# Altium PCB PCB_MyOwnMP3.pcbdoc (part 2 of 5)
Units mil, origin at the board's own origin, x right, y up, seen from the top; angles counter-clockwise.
Board outline 3605 x 4860 mil, 6 copper layers (Top Layer, Inner1, Inner2, Inner3, Inner4, Bottom Layer); 291 components, 261 nets, 1070 pads, 1658 vias.
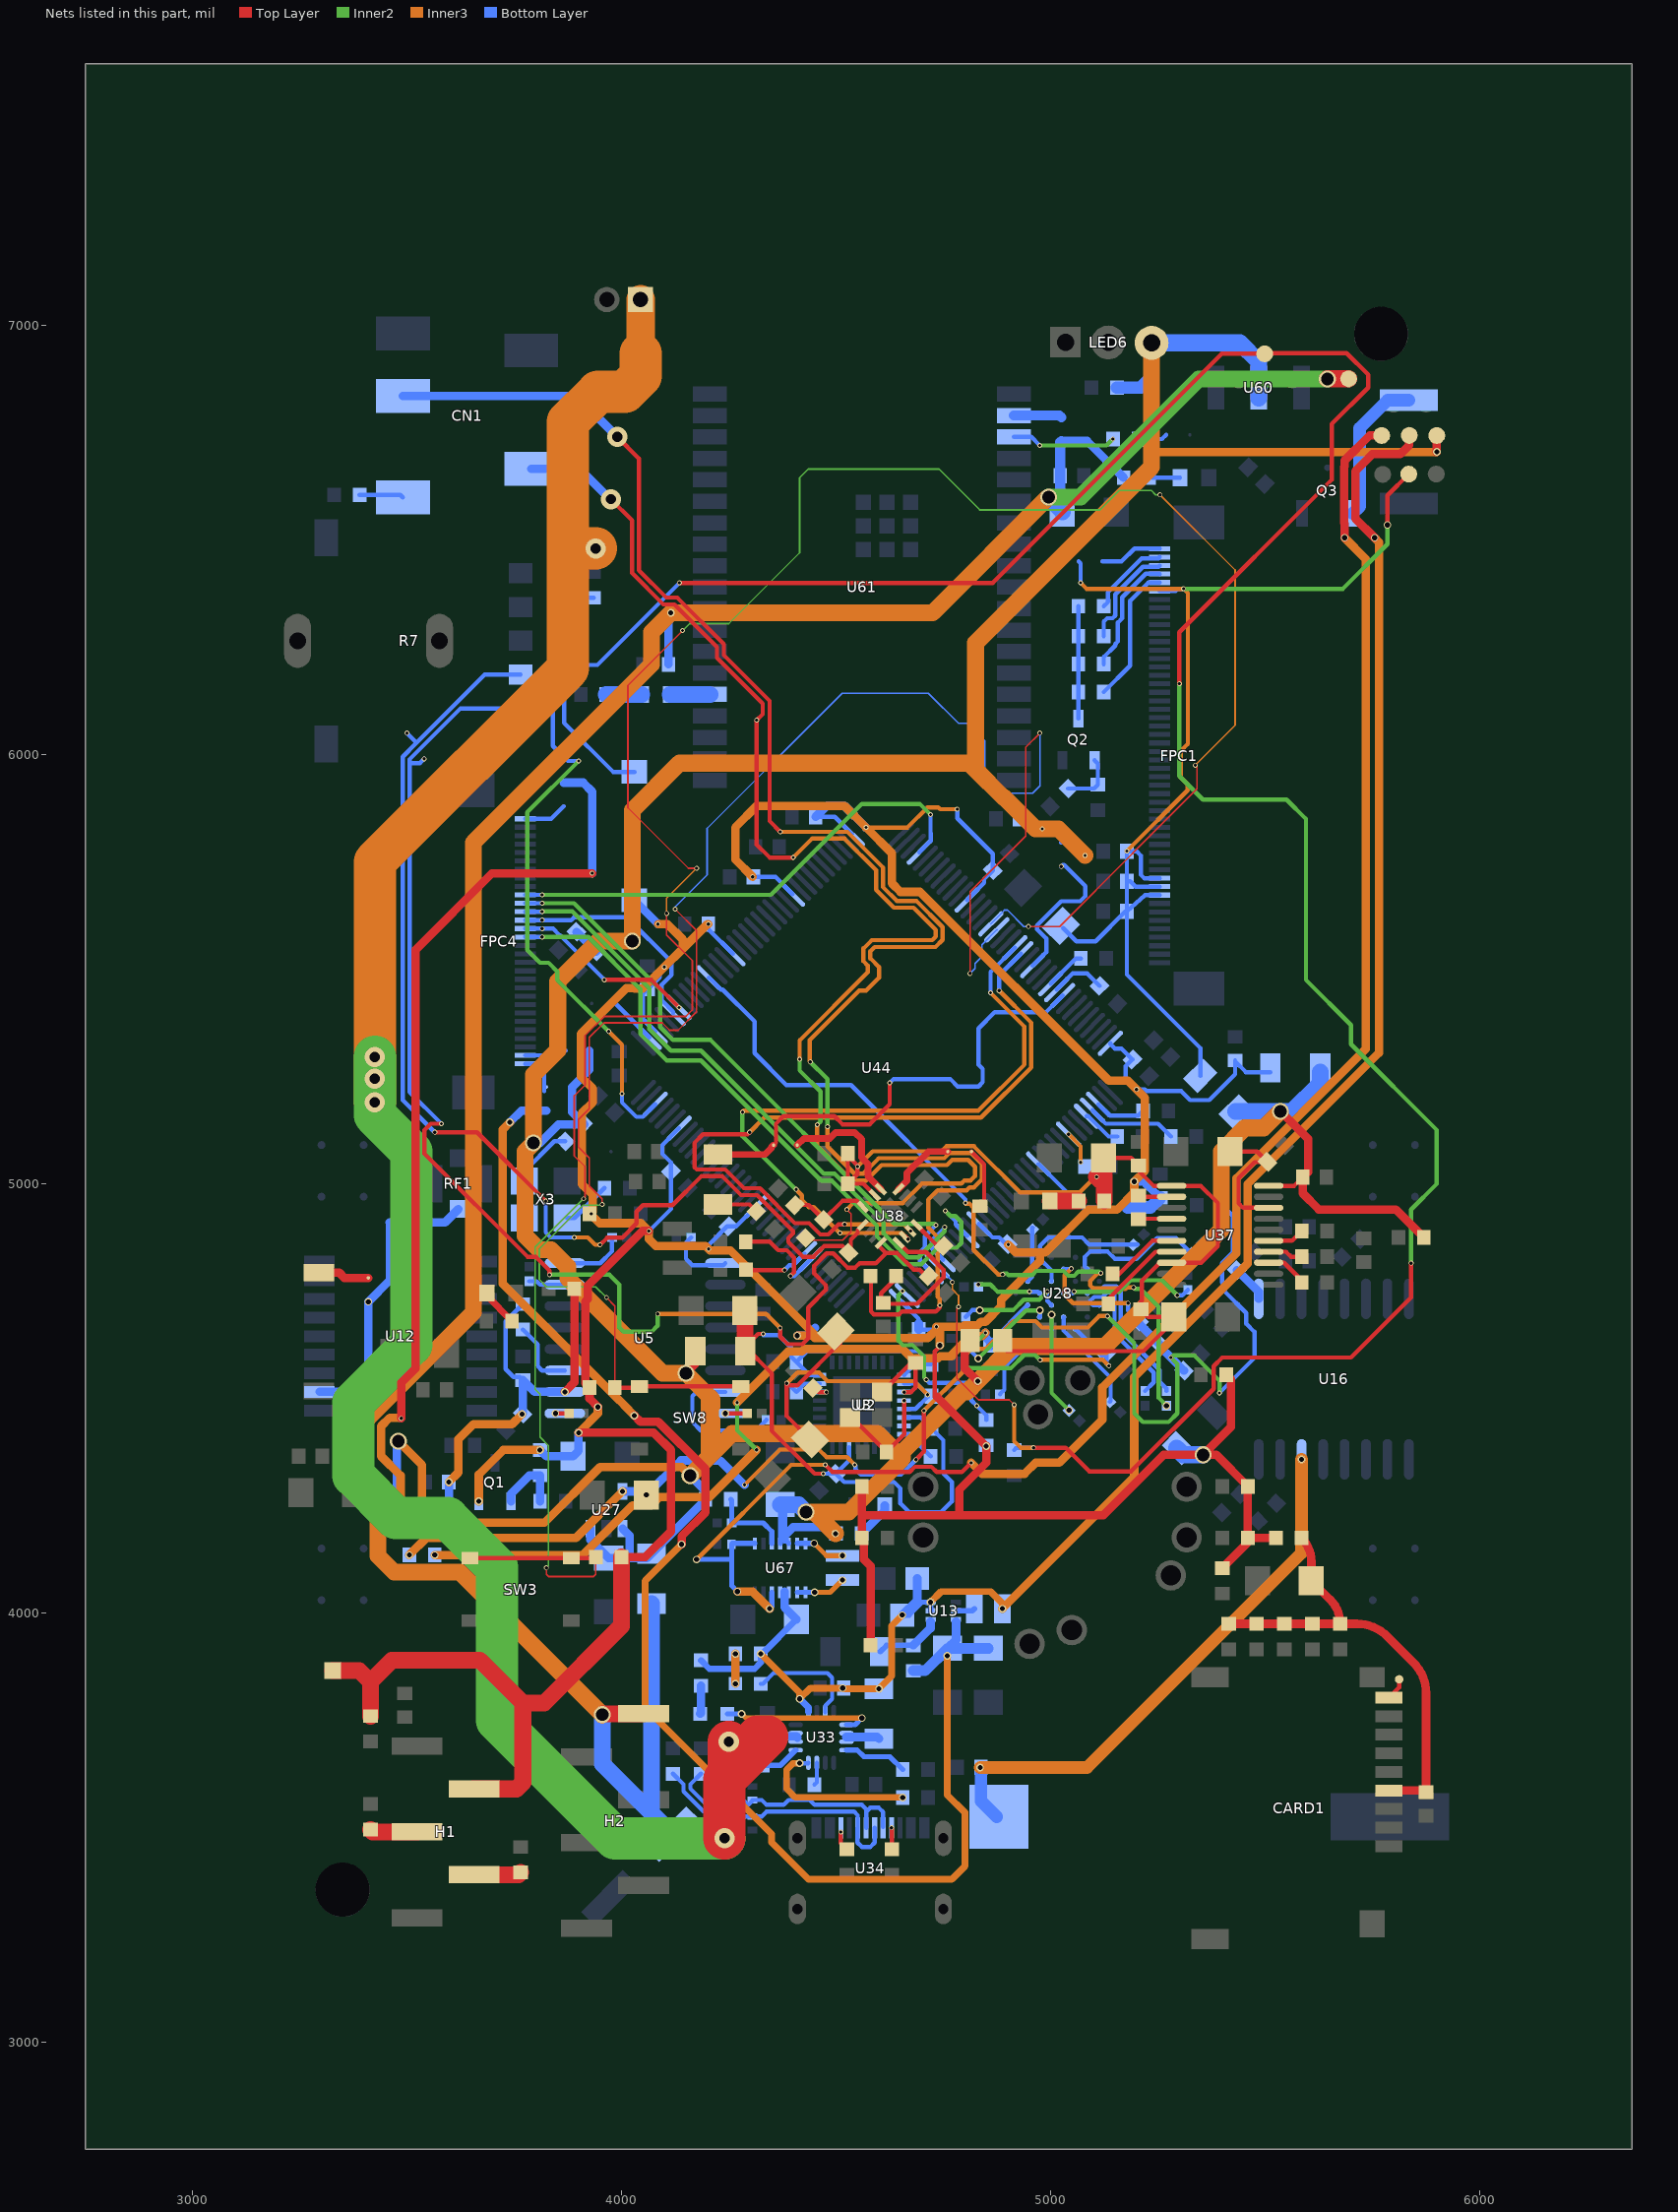
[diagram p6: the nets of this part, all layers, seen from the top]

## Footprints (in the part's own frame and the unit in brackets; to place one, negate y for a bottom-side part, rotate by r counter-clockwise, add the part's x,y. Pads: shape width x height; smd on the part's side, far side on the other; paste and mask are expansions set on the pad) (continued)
WIFI-SMD_ESP32-WROVER-E-N8R2 [mm]
  rect 2x0.9 smd: 1(-9,11.43) 2(-9,10.16) 3(-9,8.89) 4(-9,7.62) 5(-9,6.35) 6(-9,5.08) 7(-9,3.81) 8(-9,2.54) 9(-9,1.27) 10(-9,0) 11(-9,-1.27) 12(-9,-2.54) 13(-9,-3.81) 14(-9,-5.08) 15(-9,-6.35) 16(-9,-7.62) 17(-9,-8.89) 18(-9,-10.16) 19(-9,-11.43) 20(9,-11.43) 21(9,-10.16) 22(9,-8.89) 23(9,-7.62) 24(9,-6.35) 25(9,-5.08) 26(9,-3.81) 27(9,-2.54) 28(9,-1.27) 29(9,0) 30(9,1.27) 31(9,2.54) 32(9,3.81) 33(9,5.08) 34(9,6.35) 35(9,7.62) 36(9,8.89) 37(9,10.16) 38(9,11.43)
  rect 0.9x0.9 smd: 39(-2.89,2.22) 39(-2.89,3.62) 39(-2.89,5.02) 39(-1.49,2.22) 39(-1.49,3.62) 39(-1.49,5.02) 39(-0.09,2.22) 39(-0.09,3.62) 39(-0.09,5.02)
  silkscreen extent -9.72,-12.53 9,18.87
WQFN-16_L3.0-W3.0-P0.50-TL-EP1.6 [mm]
  rect 0.8x0.28 smd: 1(-1.5,0.749) 2(-1.5,0.249) 3(-1.5,-0.249) 4(-1.5,-0.749) 9(1.5,-0.749) 10(1.5,-0.249) 11(1.5,0.249) 12(1.5,0.749)
  rect 0.28x0.8 smd: 5(-0.749,-1.5) 6(-0.249,-1.5) 7(0.249,-1.5) 8(0.749,-1.5) 13(0.749,1.5) 14(0.249,1.5) 15(-0.249,1.5) 16(-0.749,1.5)
  rect 1.6x1.6 smd: 17(0,0)
  silkscreen extent -2.38,-1.72 1.72,1.72

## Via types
v1: diameter 11.42, hole 7.48, Top Layer to Bottom Layer, 1536 vias
v2: diameter 17.72, hole 11.81, Top Layer to Bottom Layer, 85 vias
v3: diameter 39.37, hole 29.53, Top Layer to Bottom Layer, 11 vias
v4: diameter 11.81, hole 7.87, Top Layer to Bottom Layer, 8 vias
v5: diameter 47.24, hole 23.62, Top Layer to Bottom Layer, 8 vias
v6: diameter 19.68, hole 11.81, Top Layer to Bottom Layer, 4 vias
v7: diameter 24.41, hole 12.2, Top Layer to Bottom Layer, 3 vias
v8: diameter 11.4, hole 7.5, Top Layer to Bottom Layer, 3 vias

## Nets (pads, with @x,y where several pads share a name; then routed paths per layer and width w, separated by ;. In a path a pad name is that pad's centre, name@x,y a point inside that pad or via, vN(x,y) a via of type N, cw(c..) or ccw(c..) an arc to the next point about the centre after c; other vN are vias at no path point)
1V8_PHY: C42.2 C43.2 C44.2 C80.2 U3.15 U3.26 U3.29 | length 947.7
  Top Layer w10: C42.2@4439.34,4404.34 4385,4458.67 v1(4385,4535) 4390,4530 4410,4530 4509.34,4629.34 C44.2@4509.34,4665.66
  Inner3 w10: v1(4385,4535) 4410,4560 4460,4560 4480,4540 4681.84,4540 v1(4713.54,4508.31)
  Bottom Layer w10: v1(4385,4535) 4387.56,4535 C43.2@4407.56,4515 4426.85,4534.29 U3.15@4461.58,4534.29 ; U3.29@4658.42,4475.16 4685.16,4475.16 4713.54,4503.54 v1(4713.54,4508.31) 4687.63,4534.21 U3.26@4658.42,4534.21
1V8_VCCQ: C73.1 C74.1 R99.2 U28.D1 U28.E4 | length 2390.2
  Inner2 w10: v1(4269.49,4490) 4269.49,4425.51 v1(4315,4380) ; v1(4848.29,4652.74) 4795,4599.45 4795,4585 4808.54,4571.46 4810.48,4571.46 4811.78,4570.16 4906.92,4570.16 4938.38,4601.62 4963.52,4601.62 v1(4975.51,4589.63)
  Inner3 w10: v1(4975.51,4589.63) 4975.88,4590 5121.69,4590 v1(5135.84,4575.84)
  Inner3 w19.68: v2(3564.66,4135) 3910,4135 4025.31,4250.31 4068.22,4250.31 4087.9,4270 4205,4270 v1(4315,4380) ; v1(4269.49,4490) 4388.82,4609.33 4420.63,4609.33 4426.3,4615 4655,4615 4676.93,4593.07 4737.62,4593.07 4742.1,4597.55 4770,4597.55 4770,4602.29 4812.71,4645 4840.55,4645 v1(4848.29,4652.74)
  Bottom Layer w10: C74.1@4860,4630.7 U28.E4@4946.48,4717.16 ; U28.D1@5057.84,4661.48 5119.83,4599.49 C73.1@5125.51,4599.49 ; C73.1@5130.51,4604.49 5130.51,4581.18 v1(5135.84,4575.84)
  Bottom Layer w19.68: v1(4848.29,4652.74) 4848.29,4642.41 4860,4630.7 C74.1@4860,4622.56
1V8_VDD: C39.2 C70.2 C71.1 C72.1 JP13.2 R99.1 R111.2 U27.5 U28.B4 | length 5916.7
  Top Layer w10: v1(4686.09,4357.16) 4704.83,4375.9 v1(4704.83,4471.22)
  Top Layer w19.68: v1(3486.57,4453.43) 3486.57,4536.57 3520,4570 3520,5545 3698.43,5723.43 v1(3931.57,5723.43)
  Inner2 w10: v1(5132.49,4691.3) 5195,4628.79 5195,4465 5215,4445 5275,4445 5295,4465 5295,4580.27 v1(5280.36,4594.91) 5285.46,4600 5335,4600 5393.46,4541.54 v1(5393.46,4512.3)
  Inner3 w10: v1(4286.57,4298.43) 4368.96,4380.83 4460,4380.83 4477.91,4362.91 4525.62,4362.91 v1(4543.53,4345) ; v1(4704.83,4471.22) 4795,4561.39 4795,4595 4815,4615 4848.61,4615 4913.61,4680 4965,4680 4980,4665 5086.39,4665 5113.09,4691.69 5132.1,4691.69 v1(5132.49,4691.3) ; v1(5048.1,4802.32) 5032.87,4787.1 5032.87,4741.01 5052.27,4721.61 v1(5180.59,4721.61)
  Inner3 w19.68: v1@3485,4455 3460,4455 3440,4435 3440,4365 3485,4320 3485,4235.34 3545.34,4175 ; v2(3505.34,4135) 3545.34,4175 ; v2(4002.4,4283.31) 3894.09,4175 3545.34,4175
  Bottom Layer w10: v1(4543.53,4345) 4545,4343.53 4545,4335 4557.5,4322.5 4651.43,4322.5 v1(4686.09,4357.16) ; U28.B4@5030,4800.68 5046.45,4800.68 v1(5048.1,4802.32) ; v1(5180.59,4721.61) 5180.59,4704.68 C71.1@5205.8,4679.48 ; v1(5393.46,4512.3) 5475,4593.84 5475,4655 5455.98,4674.02 5455.98,4699.02 5405.98,4749.02 5405.98,4763.4 5399.66,4769.73 5399.66,4814.66 5425,4840 5425,4924.66 R111.2@5399.66,4950
  Bottom Layer w19.68: JP13.2@3865,5934.53 3910.47,5934.53 3931.57,5913.43 v1(3931.57,5723.43) ; v2(4002.4,4283.31) 4049.68,4283.31 v2(4057.99,4275) 4138.5,4355.51 4174.71,4355.51 4175.22,4355 4230,4355 v1(4286.57,4298.43) ; C71.1@5205.8,4679.48 5205.8,4674.48 C72.1@5255.8,4624.48 5255.8,4619.48 v1(5280.36,4594.91) C70.2@5310.8,4564.48
3V3: C13.2 C59.2 C60.1 C61.1 C62.1 C63.1 C64.1 C65.1 C66.1 C67.1 C68.1 C69.1 C123.1 H1.4 JP4.2 JP5.2 KEY2.1 Q1.2 R15.1 R17.1 R47.2 R49.2 R50.2 R51.2 R52.1 R53.1 R54.1 R58.2 R73.2 R87.2 R88.2 TP2.1 U18.2 U29.2 U41.2 U44.17 U44.30 U44.39 U44.52 U44.62 U44.72 U44.84 U44.108 U44.131 U44.144 | length 12258.6
  Top Layer w10: 4735.07,4503.63 4730.23,4508.47 4730.23,4609.43 4741.98,4621.19 v2(4741.98,4623.22)
  Top Layer w19.68: v2(3900,4420) 4075,4420 4115,4380 4115,4190 4055,4130 R87.2@3999.66,4130 ; v2(3945,4480) 3925.34,4499.66 R88.2@3925.34,4525 3915.67,4534.67 3915.67,4725.74 3921.36,4731.44 3921.36,4762.83 4048.53,4890 v1(4063.91,4890) ; R52.1@4560.34,4295 4560.34,4227.58 ; R51.2@4580.34,3925 4580.34,4109.66 4565,4125 4565,4170.34 R49.2@4560.34,4175 4560.34,4227.58 ; 4735.07,4503.63 v2(4850,4388.7) 4850,4350 4787.58,4287.58 4787.58,4227.58 ; R73.2@5400,4104.66 5459.66,4164.32 R50.2@5459.66,4175 ; R53.1@5409.66,4555 5420,4544.66 5420,4433.04 v3(5355.44,4368.48) ; R54.1@5525.34,4175 R50.2@5459.66,4175 ; 4560.34,4227.58 4787.58,4227.58 ; 4787.58,4227.58 5122.58,4227.58 5263.48,4368.48 v3(5355.44,4368.48) ; v3(5355.44,4368.48) 5386.18,4368.48 R47.2@5459.66,4295 R50.2@5459.66,4175
  Top Layer w39.37: TP2.1@3326.8,3866.02 3388.98,3866.02 3415,3840 ; U29.2@3415,3759.66 3415,3840 ; H1.4@3656.54,3590 3755,3590 3770,3605 3770,3790 ; R87.2@3999.66,4130 3999.66,3969.66 3820,3790 3770,3790 ; 3415,3840 3465,3890 3670,3890 3770,3790
  Inner3 w10: v1(4570,5830) 4666.39,5830 4713.09,5876.69 4738.31,5876.69 4742.5,5872.5 v1(4782.5,5872.5)
  Inner3 w19.68: v2(3667.4,4260.32) 3667.4,4322.4 3724.66,4379.66 v2(3810,4379.66) ; v2(3900,4420) 3945,4465 v2(3945,4480) ; v1(4085,5605) 4106.71,5605 4142.5,5569.21 4142.5,5547.5 ; v1(4202.56,5605) 4200,5605 4142.5,5547.5 ; v1(4305.59,5715) 4265,5755.59 4265,5830 4315,5880 4520,5880 v1(4570,5830) 4630,5770 4630,5700 4650,5680 4695.73,5680 5135.73,5240 5180,5240 v4(5200,5220) 5220,5200 5220,5030 v2(5195,5005) 5195,4980 5154.49,4939.49 5087.39,4939.49 4987.9,4840 4975,4840 ; v2(4409.73,4646.24) 4448.75,4646.24 4450.56,4648.04 ; v2(4741.98,4623.22) 4741.98,4658.71 v1(4733.88,4666.82) ; v1(4901.18,4858.1) 4919.28,4840 4975,4840 ; 4142.5,5547.5 v1(4100,5505) 4050.09,5455.09 4029.98,5455.09 4029.27,5455.79 4011.43,5455.79 3905,5349.37 3905,5250 3933.19,5221.81 3933.19,5189.86 3907.87,5164.54 3907.87,4999.01 3933.19,4973.7 3933.19,4933.78 v1(3929.41,4930) 3929.41,4927.95 3949.09,4908.27 4045.64,4908.27 v1(4063.91,4890) 4063.91,4871.09 4080,4855 4195.69,4855 v1(4202.77,4847.91) 4205.69,4845 4253.6,4845 4450.56,4648.04 ; 4450.56,4648.04 4450.56,4640.67 4714.03,4640.67 4733.88,4660.52 v1(4733.88,4666.82) ; v1(4733.88,4666.82) 4795.52,4666.82 4799.37,4670.67 4829.91,4670.67 4837.65,4678.41 4847.95,4678.41 4885,4715.46 4885,4730 4975,4820 4975,4840
  Bottom Layer w10: v1(4063.91,4890) 4115.51,4941.6 C64.1@4115.51,5029.49 4115.51,5049.49 4095,5070 4095,5090 4134.26,5129.26 U44.30@4134.26,5129.41 ; U44.39@4078.59,5354.91 4050,5383.5 4050,5442.44 C69.1@4060,5452.44 4088.7,5481.14 4088.7,5493.7 v1(4100,5505) ; v1(4202.56,5605) 4202.56,5592.84 U44.52@4259.54,5535.86 ; v1(4202.77,4847.91) 4202.77,4857.25 4246.03,4900.51 C65.1@4249.49,4900.51 4267.27,4900.51 U44.17@4315.22,4948.46 ; v1(4305.59,5715) 4358.79,5715 U44.62@4398.73,5675.06 ; C61.1@4452.56,5855 4497.18,5855 U44.72@4537.93,5814.25 ; U44.144@4652.07,4725.75 4692.56,4685.26 C68.1@4692.56,4675 ; C68.1@4692.56,4660 4727.05,4660 v1(4733.88,4666.82) ; v1(4782.5,5872.5) 4782.5,5851.32 4865,5768.82 4865,5730 4845,5710 4845,5700.95 U44.84@4805.19,5661.14 ; U44.131@4833.03,4906.7 4864.73,4875 4880,4875 4896.9,4858.1 v1(4901.18,4858.1) ; U44.108@5139.25,5327.07 5139.25,5325.75 5150,5315 5165,5315 C60.1@5190.51,5289.49 5175,5273.98 5175,5245 v4(5200,5220) 5219.41,5220 5223.55,5215.86 5304.14,5215.86 5325,5195 5370,5195 5430,5255 C59.2@5430,5285 ; C59.2@5430,5287.44 C59.2@5430,5285 ; R15.1@5511.78,5260 5455,5260 C59.2@5430,5285
  Bottom Layer w19.68: v2(3810,4379.66) 3824.66,4365 C13.2@3887.3,4365 3900,4377.7 v2(3900,4420) ; KEY2.1@4030,5660.4 4085,5605.4 v1(4085,5605) ; v2(4409.73,4646.24) 4433,4646.24 4450.88,4664.12 ; C61.1@4452.56,5855 4477.56,5880 4520,5880 v1(4570,5830) ; C68.1@4692.56,4660 C68.1@4692.56,4675 ; v2(5195,5005) 5217.44,5005 5221.46,5000.98 5221.46,5000.26 5230.73,4990.99 5231.45,4990.99 C66.1@5255,4967.44
  Bottom Layer w29.53: JP4.2@5179.53,4945 5232.56,4945 C66.1@5255,4967.44
  Bottom Layer w39.37: R17.1@5293.83,4383.83 5309.19,4368.48 v3(5355.44,4368.48)
3V3_ANALOG: C28.2 C29.1 C33.2 C34.1 C81.2 C84.2 L5.1 R74.1 U37.1 U37.8 U38.14 | length 2237.4
  Top Layer w10: C81.2@4522.56,5070 C81.2@4527.56,5065 ; U38.14@4590.18,4973.69 4563.87,5000 C84.2@4527.56,5000 ; L5.1@4873.04,4635 4898.04,4610 5216.56,4610 5292.3,4685.74 5292.3,4690 5227.56,4690 C28.2@5210,4707.56 5210,4725.17 5212.91,4728.09 5212.91,4774.17 5254.77,4816.02 U37.8@5281.97,4816.02 5351.02,4816.02 5390,4855 5390,4955 5350,4995 5282.13,4995 U37.1@5281.97,4995.16 5239.84,4995.16 5205,5030 C33.2@5205,5042.44 5187.44,5060 C34.1@5122.7,5060 ; C84.2@4527.56,5000 4550,5022.44 v1(4550,5040) 4550,5042.56 C81.2@4527.56,5065 ; C84.2@4527.56,5000 C81.2@4527.56,5065
  Top Layer w39.37: v1(5107.16,5015.76) 5113.62,5009.31 5124.66,5009.31 ; C34.1@5122.7,5060 5124.66,5058.04 5124.66,5009.31 ; R74.1@5124.66,4960 5124.66,5009.31
  Inner3 w10: v1(4550,5040) 4585.55,5075.55 4745.55,5075.55 4757.36,5087.36 4821.25,5087.36 4928.44,4980.16 5068.23,4980.16 5103.84,5015.76 v1(5107.16,5015.76)
3V3_ESP32: C120.2 C121.1 H2.6 JP9.2 R27.1 R81.1 R82.1 TP25.1 U17.1 | length 6436.3
  Top Layer w39.37: v3(3955,3763.1) 3956.9,3765 H2.6@4051.54,3765 ; v3(5645,6875) 5645.44,6875.44 TP25.1@5694.45,6875.44
  Inner2 w39.37: v3(4995,6600) 5070,6600 5345,6875 v3(5645,6875)
  Inner3 w39.37: v3(3955,3763.1) 3623.1,4095 3470.39,4095 3432.16,4133.22 3432.16,4302.84 3392.79,4342.21 3392.79,4438.01 3655,4700.22 3655,5795 4070,6210 4070,6285 v2(4115,6330) 4725,6330 v3(4995,6600)
  Bottom Layer w19.68: R82.1@4109.66,6210 4109.66,6324.66 v2(4115,6330) ; JP9.2@5025,6730.47 5084.87,6730.47 R81.1@5170.34,6645
  Bottom Layer w23.62: C121.1@5022.44,6572.56 C120.2@5022.44,6650 5022.44,6727.91 JP9.2@5025,6730.47
  Bottom Layer w39.37: v3(3955,3763.1) 3955,3648.66 4070,3533.66 ; R27.1@4070,4021.78 4070,3533.66 ; U17.1@4119.33,3484.33 4070,3533.66 ; v3(4995,6600) 5022.44,6572.56 5027.3,6567.7 C121.1@5027.3,6565
3V3_IPS: C17.1 C19.1 C25.2 C26.1 FPC1.6 FPC1.40 FPC1.41 FPC1.42 JP7.2 R61.1 TP20.1 | length 2831.6
  Top Layer w10: v2(5785,6535) 5785,6603.76 TP20.1@5834.57,6653.32
  Inner2 w10: v1(5310,6386.22) 5681.22,6386.22 5785,6490 v2(5785,6535)
  Inner3 w10: v1(5070,6400) 5083.78,6386.22 v1(5310,6386.22) 5320,6376.22 5320,6025 5303.25,6008.25 5303.25,5946.75 5319.21,5930.79 5319.21,5916.65 v1(5177.56,5775)
  Bottom Layer w10: C25.2@5029.34,5595.66 5060,5565 5105,5565 5175,5635 C26.1@5177.56,5635 C19.1@5177.56,5705 v1(5177.56,5775) 5200,5775 5210,5765 5210,5720 5218.1,5711.9 FPC1.40@5254.35,5711.93 ; JP7.2@5065.47,6450 5070,6445.47 v1(5070,6400) ; C19.1@5177.56,5705 5185,5705 5197.7,5692.3 FPC1.41@5254.3,5692.3 ; FPC1.42@5254.31,5672.57 5220,5672.6 C26.1@5177.56,5635 5177.6,5487.4 5348.8,5316.2 R61.1@5348.83,5251.17 ; FPC1.6@5254.35,6381.22 5291.22,6381.22 5296.22,6386.22 v1(5310,6386.22)
3V3_PHY: C45.2 C46.1 C47.1 C48.1 C49.1 R30.2 U3.6 U3.16 U3.25 U3.30 U3.31 | length 1857
  Top Layer w10: v1(4330.22,4650.22) 4318.44,4650.22 4288.22,4620 4350,4558.22 4350,4424.49 4450,4324.49 v1(4470,4324.49)
  Top Layer w39.37: C45.2@4287.7,4715 4287.7,4620.52 R30.2@4288.22,4620
  Bottom Layer w10: v1(4330.22,4650.22) 4330.22,4647.25 4366.36,4647.25 4395,4618.61 4395,4597.56 C46.1@4407.56,4585 ; U3.16@4461.58,4553.98 4438.58,4553.98 C46.1@4407.56,4585 ; v1(4470,4324.49) C48.1@4499.49,4324.49 ; U3.6@4530.53,4386.58 4530.53,4355.53 C48.1@4499.49,4324.49 ; U3.31@4658.42,4435.79 U3.30@4658.42,4455.47 4696.97,4455.47 C49.1@4722.44,4430 4750,4402.44 4750,4325 4770,4305 4770,4260 4745,4235 4670,4235 4650,4255 4650,4290 4635,4305 4518.98,4305 C48.1@4499.49,4324.49 ; U3.25@4658.42,4553.9 4684.52,4580 C47.1@4722.44,4580 4692.29,4610.15 4432.71,4610.15 C46.1@4407.56,4585
3V3_QSPI: C20.1 C21.1 C22.2 R41.2 U5.2 U26.1 U69.1 | length 1025.6
  Top Layer w19.68: v2(3867.98,4515) 3890,4537.02 3890,4754.66 U26.1@3889.66,4755
  Inner3 w19.68: v2(3597.56,4305) 3620,4327.44 3620,4405 3655,4440 3745,4440 v2(3768.1,4463.1)
  Bottom Layer w10: C22.2@3770,4542.44 3762.44,4550 3748.3,4550 3730,4568.3 3730,4679.66 U69.1@3770,4719.66
  Bottom Layer w19.68: R41.2@3593.22,4220 3597.56,4224.34 v2(3597.56,4305) ; v2(3768.1,4463.1) 3770,4465 C22.2@3770,4542.44 3797.44,4515 v2(3867.98,4515)
3V3_SD: C18.2 C32.2 CARD1.4 R1.2 R2.2 R3.2 R4.2 R13.2 R54.2 | length 1094.3
  Top Layer w19.68: R1.2@5415,3974.66 R2.2@5480,3974.66 R4.2@5545,3974.66 R3.2@5610,3974.66 R13.2@5675,3974.66 ; R54.2@5584.66,4175 cw(c5529.04,4119.38) 5607.7,4119.38 C32.2@5607.7,4075 5651.64,4031.06 cw(c5595.23,3974.66) R13.2@5675,3974.66 ; CARD1.4@5788.66,3586.34 5866.22,3586.34 C18.2@5875,3577.56 ; C18.2@5875,3582.56 5875,3813.58 ccw(c5775,3813.58) 5845.71,3884.29 5784.63,3945.37 ccw(c5713.92,3874.66) 5713.92,3974.66 R13.2@5675,3974.66
3V3_VDD: C30.1 C38.2 C122.2 C124.2 JP3.2 JP14.2 L5.2 LED6.3 R15.2 R26.1 R27.2 R30.1 R38.1 R39.1 R41.1 R61.2 R70.2 R75.1 R86.2 R112.2 TP1.1 U27.1 U27.3 U37.20 U60.2 U67.4 U67.5 | length 11510.2
  Top Layer w10: U37.20@5508.03,4995.16 5567.6,4995.16 C30.1@5587.44,5015
  Top Layer w19.68: v3(4150,4558.5) 4171.78,4580.28 R30.1@4171.78,4620 ; L5.2@4811.96,4635 4800,4623.04 4800,4570 v2(4830,4540) ; v3(5535.38,5168.83) 5535.85,5168.83 5600,5104.69 5600,5027.56 C30.1@5587.44,5015 5587.44,4977.56 5625,4940 5804.66,4940 R70.2@5869.66,4875 ; TP1.1@5899.81,6743.23 5900,6743.04 v2(5900,6705)
  Inner3 w19.68: v3(3480,4400) 3535,4345 3535,4255 3580,4210 3820,4210 3950,4340 4140,4340 v3(4160,4320) ; 4195,4355 4195,4513.5 ; 5235.3,6707.33 5237.63,6705 v2(5900,6705)
  Inner3 w39.37: v3(4160,4320) 4195,4355 4210.56,4370.56 ; v3(4430,4235) v3@4448.5,4235 ; v2(4498.5,4185) v3@4448.5,4235 ; 4890,5900 4825,5965 ; 4891.72,5900 4965.02,5826.69 v1(4980.55,5826.69) 5018.31,5826.69 v1(5080,5765) ; LED6.3@5235.3,6959.19 5235.3,6707.33 5235.3,6670.3 4825,6260 4825,5965 ; 5495,5130 5452.45,5130 5397.67,5075.22 5397.67,4892.67 5227.6,4722.6 5227.6,4722 5126.6,4621.01 4911.01,4621.01 v2(4830,4540) 4805.31,4515.31 4795.31,4515.31 4654.76,4374.76 4654.76,4359.76 ; 5496.55,5130 v3(5535.38,5168.83) ; 4210.56,4370.56 4210.56,4447.64 4207.49,4450.7 4207.49,4479.3 4210.56,4482.36 4210.56,4497.94 4195,4513.5 v3(4150,4558.5) 4095.88,4558.5 3874.65,4779.72 3874.65,4806.93 3835.57,4846.01 3808.37,4846.01 3775.22,4879.15 3775.22,5075.22 v3(3795,5095) 3795,5254.56 3851.47,5311.04 3851.47,5471.47 3945,5565 v3(4025,5565) 4025,5870 4135,5980 4810,5980 4825,5965 ; 4210.56,4370.56 4257.96,4417.96 4596.56,4417.96 4654.76,4359.76 ; v3@4448.5,4235 4530,4235 4654.76,4359.76
  Bottom Layer w10: C122.2@4927.56,5850 4950.87,5826.69 v1(4980.55,5826.69) ; JP3.2@5025,5794.53 5050.47,5794.53 v1(5080,5765)
  Bottom Layer w11.81: U67.4@4370,4162.09 C124.2@4370,4252.3 4380,4242.3 4380,4180 ; 4380,4171.78 U67.5@4389.69,4162.09
  Bottom Layer w19.68: R41.1@3476.78,4220 3476.78,4396.78 v3(3480,4400) ; v3(3795,5095) 3810,5095 3853.11,5138.11 3913.84,5138.11 3885,5166.95 3885,5225.46 3924.53,5264.99 JP14.2@3924.53,5310 ; R38.1@3895.01,5586.93 R39.1@3940.97,5540.97 3965,5565 v3(4025,5565) ; U27.3@3927.6,4196.69 3927.6,4170.1 C38.2@3970,4127.7 4018.86,4127.7 ; U27.1@4002.4,4196.69 4018.86,4180.23 4018.86,4127.7 ; v3(4160,4320) 4195.34,4284.66 R112.2@4195.34,4265 4195.34,4263.56 R27.2@4070,4138.22 4059.48,4127.7 4018.86,4127.7 ; 4380,4171.78 4380,4180 4400,4200 4485.34,4200 R26.1@4500.34,4185
  Bottom Layer w29.53: R75.1@5154.66,6855 5210,6855 5235.3,6880.3 LED6.3@5235.3,6959.19
  Bottom Layer w39.37: C124.2@4370,4252.3 4412.7,4252.3 v3(4430,4235) ; LED6.3@5235.3,6959.19 5440.81,6959.19 5485,6915 U60.2@5485,6830 ; R61.2@5431.17,5168.83 v3(5535.38,5168.83) 5563.83,5168.83 5628.22,5233.22 R15.2@5628.22,5260
$1N16: R22.2 R25.2 U13.1 | length 154.8
  Bottom Layer w13: R25.2@4603.22,3910 4617.88,3924.66 R22.2@4680,3924.66
  Bottom Layer w20: R22.2@4680,3924.66 4720,3964.66 U13.1@4720,3980
$1N23: JP1.1 JP2.2 U12.11 | length 518.2
  Bottom Layer w19.68: U12.11@3296.02,4515.08 3390.08,4515.08 3410,4535 v2(3410,4725) 3460,4775 3460,4909.41 JP1.1@3459.41,4910
$1N36: BAT1.2 C12.1 U16.14 | length 1304.7
  Inner3 w29.53: v2(4835.59,3640) 5085,3640 5585,4140 v2(5585,4357.98)
  Bottom Layer w29.53: C12.1@4837.56,3640 4837.56,3561.73 BAT1.2@4874.29,3525
$1N42: Q1.1 R21.2 U18.1 | length 162.9
  Bottom Layer w19.68: Q1.1@3742.6,4260.32 3742.6,4277.6 3785.34,4320.34 U18.1@3810,4320.34 3810.34,4320 R21.2@3810.34,4260
$1N68: R55.1 U44.9 | length 142.8
  Top Layer w10: R55.1@4300,4800 4301.08,4798.92 v1(4379.87,4798.92)
  Bottom Layer w10: v1(4379.87,4798.92) 4390.95,4810 4399.47,4810 U44.9@4426.57,4837.1
$1N69: R56.1 U44.8 | length 226.5
  Top Layer w10: R56.1@4299.66,4865 4345,4865 4365,4845 4385,4845 4401.95,4828.05 4401.95,4793.5 v1(4393.62,4785.17)
  Bottom Layer w10: v1(4393.62,4785.17) 4402.47,4785.17 U44.8@4440.49,4823.19
$1N85: JP6.1 U44.38 | length 111.7
  Bottom Layer w10: JP6.1@3985.66,5420 U44.38@4064.67,5340.99
$1N87: KEY2.2 TP17.1 U40.2 U44.138 | length 6970
  Top Layer w3.94: v1(4785.3,4713.02) 4781.36,4709.09 4781.36,4546.98 4831.68,4496.66 4903.64,4496.66 v1(4915.3,4485)
  Top Layer w10: v1(4135,6400) 4865,6400 5398.64,6933.64 TP17.1@5499.02,6933.64 ; v1(4960.3,4385) 5035,4385 5090,4330 5187.55,4330 5380,4522.45 5380,4575 5400,4595 5700,4595 5840,4735 v1(5840,4815) ; v1(5300,6165) 5300,6285 5655,6640 5655,6770 5740,6855 5740,6885 5690,6935 TP17.1@5500.37,6935
  Top Layer w19.68: TP17.1@5499.02,6933.64 TP17.1@5500.37,6935
  Inner2 w10: v1(5300,6165) 5300,5950 5355,5895 5550,5895 5595,5850 5595,5475 5700,5370 5700,5325 5900,5125 5900,5000 5840,4940 v1(5840,4815)
  Inner3 w3.94: v1(4771.01,4770.58) 4771.01,4753.99 4785.3,4739.7 v1(4785.3,4713.02)
  Inner3 w10: v1@4915,4485 4915,4400 4930,4385 v1(4960.3,4385)
  Bottom Layer w3.94: U44.138@4735.59,4809.26 4771.01,4773.84 v1(4771.01,4770.58)
  Bottom Layer w10: KEY2.2@4030,5959.6 3980.4,5959.6 3865.98,6074.02 3865.98,6173.38 3901.3,6208.7 3943.7,6208.7 v1(4135,6400) ; U40.2@4915,4379.66 4920.34,4385 v1(4960.3,4385)
$1N183: R86.1 X3.1 X3.4 | length 233.6
  Bottom Layer w10: X3.1@3773.31,5006.62 3773.31,5028.86 3843.48,5099.03 R86.1@3869.03,5099.03
  Bottom Layer w19.68: X3.4@3773.31,4920 X3.1@3773.31,5006.62
$1N185: R89.1 U44.98 | length 94.6
  Bottom Layer w10: U44.98@5000.06,5466.26 5058.8,5525 R89.1@5070.34,5525
$1N186: R90.1 U44.99 | length 127.7
  Bottom Layer w10: U44.99@5013.98,5452.35 5051.63,5490 5085,5490 R90.1@5114.03,5460.97
$1N187: R91.1 U44.116 | length 77.2
  Inner3 w10: v1(5041.81,5115.49) 5070.06,5087.24 v1(5070.06,5050)
$1N188: R94.1 U44.111 | length 119.6
  Bottom Layer w10: U44.111@5111.41,5185.09 5137.93,5158.57 5203.91,5158.57 R94.1@5215.34,5170
$1N189: R92.1 U44.113 | length 91.3
  Bottom Layer w10: U44.113@5083.58,5157.25 5088.08,5157.25 5135.33,5110 R92.1@5155.34,5110
$1N190: R93.1 U44.112 | length 208.2
  Bottom Layer w10: U44.112@5097.49,5171.17 5128.66,5140 5250.34,5140 R93.1@5280.34,5110
$1N3471: R44.1 U5.16 | length 50.9
  Top Layer w10: v2(4242.02,4465) R44.1@4292.96,4465
$1N3472: R43.1 U5.15 | length 332.8
  Bottom Layer w10: U5.15@4242.02,4515 4175,4515 4165,4505 4165,4445 4185,4425 4312.96,4425 R43.1@4337.96,4450
$1N3473: R109.1 U5.9 | length 155.2
  Bottom Layer w10: R109.1@4162.04,4875 4150.08,4863.04 4150.08,4824.92 4165.01,4809.99 4237.05,4810.03 U5.9@4242.02,4815
$1N3474: R42.2 U5.8 | length 153.6
  Bottom Layer w10: U5.8@3867.98,4815 3950,4815 3977.96,4842.96 R42.2@3977.96,4875
$1N3475: R46.2 U5.7 | length 86.3
  Bottom Layer w10: R46.2@3785,4772.96 3802.04,4772.96 3810,4765 U5.7@3867.98,4765
$1N3476: U5.3 U69.2 | length 167
  Bottom Layer w10: U69.2@3770,4660.34 3805,4625.34 3805,4575 3815,4565 U5.3@3867.98,4565
$1N3478: R45.2 U5.1 | length 32
  Top Layer w10: v2(3845.98,4465) R45.2@3877.96,4465
$1N3479: H1.2 R19.2 | length 110.7
  Top Layer w39.37: H1.2@3656.54,3390 3759.66,3390 R19.2@3765,3395.34
$1N3480: H1.3 R20.2 | length 110.7
  Top Layer w39.37: R20.2@3415,3495.34 3420.34,3490 H1.3@3523.47,3490
$1N3521: R9.2 U16.1 | length 88.1
  Bottom Layer w19.68: R9.2@5434.03,4799.03 5485,4748.05 U16.1@5485,4732.02
$1N3524: JP1.2 RF1.1 | length 118.3
  Bottom Layer w19.68: JP1.2@3514.53,4910 3589.05,4910 RF1.1@3620,4940.95
$1N3525: JP2.1 L2.1 | length 120.1
  Top Layer w19.68: L2.1@3295,4792.79 3342.21,4792.79 3354.41,4780.59 JP2.1@3410,4780.59
$1N3542: LED1.1 R26.2 | length 87.3
  Bottom Layer w19.68: R26.2@4559.66,4185 4613.46,4238.8 LED1.1@4613.46,4250
$1N3543: R23.2 U19.1 | length 89.1
  Top Layer w15.75: U19.1@3686.54,4745 3686.54,4738.12 R23.2@3744.66,4680
$1N3562: R105.2 U28.A3 | length 326.4
  Bottom Layer w10: U28.A3@5085.68,4800.68 5080,4806.36 5080,4830 5091.97,4841.97 5133.03,4841.97 5150,4825 5200,4825 5248.42,4873.42 5292.48,4873.42 R105.2@5327.95,4837.95
$1N3563: R106.2 U28.B2 | length 365.9
  Bottom Layer w10: U28.B2@5085.68,4745 5090.68,4750 5115.12,4750 5125.73,4760.61 5153.12,4760.61 5163.12,4750.61 5163.12,4656.59 5253.94,4565.77 5253.94,4538.88 5270,4522.81 R106.2@5270,4517.04
$1N3564: R107.2 U28.B1 | length 366.3
  Bottom Layer w10: U28.B1@5113.52,4717.16 5099.38,4717.16 5090.83,4725.71 5101.19,4736.06 5120.9,4736.06 5131.5,4746.67 5144.94,4746.67 5149.19,4742.42 5149.19,4650.81 5240,4560 5240,4537.04 R107.2@5220,4517.04
$1N3565: R108.2 U28.C3 | length 322.4
  Inner2 w10: v1(5054.57,4748.64) 5159.95,4748.64 5186.39,4775.09 5259.91,4775.09 v1(5295,4740)
  Bottom Layer w10: U28.C3@5030,4745 5050.92,4745 v1(5054.57,4748.64) ; v1(5295,4740) 5307.04,4740 R108.2@5320,4752.96
$1N3566: R104.1 U28.E1 | length 229.7
  Bottom Layer w10: R104.1@4882.04,4510 4892.04,4520 4892.04,4572.04 4930,4610 5006.36,4610 U28.E1@5030,4633.64
$1N3567: R103.1 U28.E2 | length 269.2
  Inner2 w10: v2(5002.16,4695) 5002.16,4512.84 v2@5040,4475
  Bottom Layer w10: U28.E2@5002.16,4661.48 v2(5002.16,4695)
  other v2: 5042.95,4472.05
$1N3568: R102.1 U28.E3 | length 265.2
  Inner2 w10: v2(4831.15,4593.04) 4943.11,4705 v2(4975,4705)
  Bottom Layer w10: R102.1@4802.04,4640 4802.04,4622.15 v2(4831.15,4593.04) ; U28.E3@4974.32,4689.32 4975,4690 v2(4975,4705)
$1N3569: R101.1 U28.D5 | length 129.9
  Bottom Layer w10: U28.D5@4946.48,4772.84 4957.04,4783.4 4957.04,4897.04 R101.1@4957.95,4897.95
$1N3570: R100.1 U28.D4 | length 151.1
  Inner2 w10: v1(4831.66,4765.27) 4859.73,4765.27 4876.41,4748.59 v1(4950.89,4748.59)
  Bottom Layer w10: v1(4950.89,4748.59) 4970.73,4748.59 U28.D4@4974.32,4745
$1N3571: R97.1 U28.C4 | length 336.6
  Bottom Layer w10: U28.C4@5002.16,4772.84 5002.16,4797.84 4975,4825 4975,4855 4994.84,4874.84 5073.22,4874.84 5090.11,4857.95 R97.1@5202.95,4857.95
$1N3572: R96.1 U28.D2 | length 243.7
  Bottom Layer w10: U28.D2@5030,4689.32 5030,4658.08 5140,4548.08 5140,4494.1 R96.1@5137.95,4492.05
$1N3573: R95.1 U28.D3 | length 250.1
  Inner2 w10: v2(4835.08,4705.44) 4912.84,4705.44 4937.24,4729.84 4973.57,4729.84 v1(4992.31,4748.58)
  Bottom Layer w10: R95.1@4802.04,4690 4805.46,4693.42 4805.63,4693.42 4815.41,4703.2 4815.41,4703.37 4817.48,4705.44 v2(4835.08,4705.44) ; v1(4992.31,4748.58) 4992.31,4727.01 U28.D3@5002.16,4717.16
$1N3616: JP3.1 U44.95 | length 357.7
  Bottom Layer w10: U44.95@4958.3,5508.03 4989.82,5539.55 4989.82,5571.54 4968.63,5592.73 4968.63,5601.83 5024.84,5658.04 5068.66,5658.04 5081.18,5670.56 5081.18,5693.23 5031.33,5743.08 5028.67,5743.08 v4(5025,5739.41)
$1N3621: JP4.1 U44.121 | length 194
  Bottom Layer w10: U44.121@4972.22,5045.9 5073.1,4945 JP4.1@5124.41,4945
$1N3624: U41.1 U44.143 | length 453.5
  Inner2 w10: v1(4655,4750) 4644.82,4739.82 4644.82,4635 4655.94,4623.88 ; 4655.98,4623.93 4678.68,4623.93 4705.12,4597.49 4705.12,4548.49 v1(4710.26,4543.34)
  Bottom Layer w10: v1(4710.26,4543.34) 4717.11,4536.5 4803.5,4536.5 4815,4525 4815,4495.72 v1(4827.73,4483) 4850,4460.72 U41.1@4850,4449.66
$1N3651: R85.1 X3.3 | length 116
  Bottom Layer w10: X3.3@3873.31,4920 3890.34,4920 R85.1@3960.34,4990
$1N12314: R112.1 R113.1 U67.3 | length 185.3
  Bottom Layer w11.81: R112.1@4254.66,4265 4257.04,4262.62 R113.1@4257.04,4210 4330,4210 4350.32,4189.68 U67.3@4350.32,4162.09
$1N12583: C127.2 TP12.1 U67.1 U67.12 | length 4129.8
  Top Layer w10: v1(4475,4345) 4491.69,4328.31 4671.52,4328.31 4683.68,4340.47 4722.14,4340.47 4734.3,4328.31 4793.31,4328.31 v1(4815,4350)
  Top Layer w19.68: v2(5685,6505) 5685,6538.7 5684.33,6539.37 5684.33,6670.63 5685,6671.3 5685,6685 5743.32,6743.32 TP12.1@5771.37,6743.32
  Inner3 w10: v2(4175,4124.61) 4395.39,4345 v1(4475,4345)
  Inner3 w19.68: v1(4815,4350) 4840.59,4324.41 4939.41,4324.41 4965,4350 5020,4350 5120.32,4450.32 5120.32,4525.32 5433.18,4838.18 5433.18,5012.63 5734.17,5313.63 5734.17,6455.83 v2(5685,6505)
  Inner3 w20: v2(4270,4050) 4305,4050 v2(4345,4010)
  Bottom Layer w11.81: v2(4175,4124.61) 4256.54,4124.61 ; v2(4270,4050) 4256.54,4063.46 4256.54,4124.61 ; U67.1@4310.94,4162.09 4258.63,4162.09 C127.2@4256.54,4160 4256.54,4124.61 ; v2(4345,4010) 4350.32,4015.32 U67.12@4350.32,4047.91
$1N12675: L7.2 U67.8 U67.9 | length 117.5
  Inner3 w12: v2(4450,4047.91) 4486.46,4047.91 v2(4515,4076.45)
  Bottom Layer w12: U67.9@4409.37,4047.91 U67.8@4429.06,4047.91 v2(4450,4047.91)
$1N12689: L7.1 U67.6 U67.7 | length 117.5
  Inner3 w12: v2(4449.06,4162.09) 4477.61,4133.55 v2(4515,4133.55)
  Bottom Layer w12: U67.6@4409.37,4162.09 U67.7@4429.06,4162.09 v2(4449.06,4162.09)
$1N13209: U13.5 U68.1 | length 44.9
  Bottom Layer w13: U13.5@4779.53,4004.99 4817.39,4004.99 U68.1@4822.4,4010
$1N24923: CARD1.9 TP13.1 | length 52.2
  Top Layer w10: CARD1.9@5788.66,3802.88 5812.32,3826.54 TP13.1@5812.32,3845.26
$2N3: C41.1 U2.1 U3.27 | length 188.3
  Top Layer w10: U2.1@4607.4,4514.53 C41.1@4675,4582.4 ; v4(4658.42,4514.53) 4674.53,4514.53 4685,4525 4685,4572.44 C41.1@4675,4582.44
$2N6: C40.2 U2.3 U3.28 | length 255.1
  Top Layer w10: U2.3@4532.6,4455.47 4537.09,4455.47 C40.2@4617.56,4375 4658.42,4415.86 v4(4658.42,4494.84)
$2N16: R29.2 U3.32 | length 83.1
  Bottom Layer w10: U3.32@4658.42,4416.1 4669.24,4416.1 R29.2@4720.34,4365
$2N34: D3.2 R24.2 U34.A7 U34.B7 | length 632.3
  Bottom Layer w10: R24.2@4185,3625.34 4160.5,3600.84 4160.5,3590.84 4198.34,3553 4223.34,3553 4235.61,3565.27 4283.34,3565.27 4295.61,3553 4305,3562.39 D3.2@4305,3564.26 4326.81,3564.26 4338.07,3553 4378,3553 4389.26,3564.26 4438.69,3564.26 4449.95,3553 4559.93,3553 4569.93,3543 4569.93,3536.31 ; 4569.92,3536.3 4569.93,3534.13 ; U34.A7@4570.16,3499.49 4570.16,3533.9 4569.93,3534.13 ; U34.B7@4609.29,3501.64 4609.76,3502.11 4609.76,3536.14 4599.76,3546.14 4579.76,3546.14 4569.93,3536.31 ; 4569.93,3534.13 4569.93,3536.31
$2N37: D4.2 R28.1 U34.A6 U34.B6 | length 636.2
  Bottom Layer w10: R28.1@4120,3625.34 4144.5,3600.84 4144.5,3584.21 4191.71,3537 4271.93,3537 4283.19,3525.74 D4.2@4305,3525.74 4326.81,3525.74 4338.07,3537 4542.14,3537 4550.47,3528.67 U34.B6@4550.47,3499.49 4550,3499.02 4550,3465 4560,3455 4580,3455 4589.84,3464.84 U34.A6@4589.84,3499.49
$2N62: R59.2 U3.14 | length 35.3
  Top Layer w10: R59.2@4445.97,4524.03 4450.97,4524.03 4460.47,4514.53 v1(4477.32,4514.53)
$2N64: U6.2 U33.15 | length 53.2
  Bottom Layer w10: U6.2@4449.66,3600 4455.17,3605.51 U33.15@4455.17,3650.94
$2N65: R31.1 U33.10 U33.11 | length 77.9
  Bottom Layer w20: 4523.91,3711.09 4595.69,3711.09 R31.1@4600,3706.78
$2N1532: U20.2 U33.1 | length 91
  Bottom Layer w13: U20.2@4329.66,3645 4370.49,3645 U33.1@4405.95,3680.46
$2N1545: R32.2 U33.16 | length 380.7
  Inner3 w15: v2(4415,3650) 4400,3650 4385,3635 4385,3590 4405,3570 v2(4655.34,3570)
  Bottom Layer w10: v2(4415,3650) 4434.54,3650 U33.16@4435.48,3650.94
$2N1546: R33.2 U33.12 | length 150.1
  Bottom Layer w12: U33.12@4524.06,3680.46 4549.54,3680.46 4565,3665 4625.34,3665 R33.2@4655.34,3635
$2N1551: LED3.1 U33.7 | length 268
  Bottom Layer w10: LED3.1@4324.48,3834.86 4329.48,3834.86 4354.62,3860 4480,3860 4490.83,3849.17 4490.83,3799.89 4474.85,3783.91 U33.7@4474.85,3769.05
$2N1552: LED3.2 R34.2 | length 69.9
  Inner3 w19.68: v2(4265.34,3905) 4265.51,3904.83 v2(4265.51,3835.14)
$2N1555: LED4.1 U33.9 | length 360
  Inner3 w12: v2(4280,3764.86) 4289.86,3755 v2(4560,3755)
  Bottom Layer w12: LED4.1@4246.48,3764.86 v2(4280,3764.86) ; U33.9@4524.06,3739.52 4544.52,3739.52 v2(4560,3755)
$2N1556: LED4.2 R35.2 | length 65.8
  Bottom Layer w19.68: LED4.2@4183.53,3765.14 4185,3766.61 R35.2@4185,3830.34
$2N1557: R36.2 U34.B5 | length 45.6
  Top Layer w10: v1(4511.1,3489.49) 4511.1,3463.56 R36.2@4525,3449.66
$2N1558: R37.2 U34.A5 | length 50.2
  Top Layer w10: v1(4629.21,3499.49) 4630,3498.7 R37.2@4630,3449.66
$3N21: Q2.3 R63.1 R64.1 R65.1 R66.1 | length 262.2
  Bottom Layer w10: R66.1@5064.63,6345.71 R65.1@5064.63,6275.71 R64.1@5064.63,6210.71 R63.1@5064.63,6145.71 5065,6145.34 Q2.3@5065,6083.62
$3N60: C37.1 C75.2 U37.18 | length 313.9
  Top Layer w10: C37.1@5417.7,5075 5481.03,5075 C75.2@5505.51,5050.51 5475.51,5050.51 5437.95,5012.95 5437.95,4954.65 5448.63,4943.98 U37.18@5508.03,4943.98
$3N63: R71.2 U37.6 | length 181.4
  Top Layer w10: R71.2@5134.66,4785 5155,4785 5237.2,4867.2 U37.6@5281.97,4867.2
$3N64: R72.2 U37.7 | length 204.5
  Top Layer w10: R72.2@5134.66,4720 5134.66,4731.58 5244.68,4841.6 U37.7@5281.97,4841.61
$3N76: C79.2 JP17.1 | length 143.8
  Top Layer w10: JP17.1@4815.59,5075 4845,5045.59 4845,4957.56 C79.2@4835,4947.56
$3N80: C2.1 R7.5 U38.1 | length 2702.9
  Top Layer w10: v1(3565,5120) 3663.31,5120 v1(3823.31,4960) ; v1(3950,4857.6) 3966.42,4874.02 4001.62,4874.02 4035,4907.39 4035,4935 4050,4950 4118.65,4950 4185.98,5017.33 4235.06,5017.33 4278.73,4973.66 4315.93,4973.66 4399.5,4890.09 4399.5,4884.09 4388.7,4873.28 4388.7,4863.91 4422.61,4830 4447.39,4830 4472.39,4855 4515,4855 4534.49,4835.51 4534.49,4869.61 4550.3,4885.43 4550.3,4892.01 U38.1@4562.39,4904.1
  Inner3 w10: v1(3890,4875) 3921.39,4875 3938.79,4857.6 v1(3950,4857.6)
  Bottom Layer w10: v1(3500,6050) 3521.35,6028.65 3521.35,6026.35 ; v1(3565,5120) 3490,5195 3490,5995 3521.35,6026.35 ; R7.5@3764.84,6186.26 3681.26,6186.26 3521.35,6026.35 ; v1(3823.31,4960) 3823.31,4886.69 3835,4875 v1(3890,4875)
$3N81: C86.1 R7.3 U38.4 | length 3093.9
  Top Layer w10: v1(3580,5140) 3555.83,5140 3540.83,5125 3540.83,5070 3780.83,4830 3800,4830 3832.26,4797.74 v1(3832.26,4787.99) ; v1(4369.82,4663.94) 4369.82,4643.79 4387.37,4626.24 4421.24,4626.24 4435,4640 4435,4711.8 4476.37,4753.17 4476.37,4762.27 4475,4763.64 4475,4765 4449.28,4790.72 4449.28,4809.28 4477.83,4837.83 4493.41,4837.83 4494.84,4836.4 ; 4494.84,4836.33 4526.33,4804.84 4544.84,4804.84 4555,4815 4592.69,4815 4616.22,4838.53 ; U38.4@4604.11,4862.38 4600,4858.3 4600,4854.76 4616.22,4838.53 ; C86.1@4715.51,4784.49 4710.5,4784.5 4695,4800 4680.86,4800 4642.32,4838.53 4616.22,4838.53
  Inner2 w10: v1(3832.26,4787.99) 3972.01,4787.99 3995,4765 3995,4665 4005,4655 4070,4655 4084.41,4669.41 v1(4084.41,4696.61)
  Inner3 w10: v1(4084.41,4696.61) 4336.17,4696.61 4338.78,4694 4339.76,4694 v1(4369.82,4663.94)
  Bottom Layer w10: v1(3540,5990) 3530,5980 3505.98,5980 ; v1(3580,5140) 3505.98,5214.02 3505.98,5980 ; R7.3@3764.84,6107.52 3625.13,6107.52 3505.98,5988.38 3505.98,5980
$3N83: C78.2 U38.8 | length 83.4
  Top Layer w10: U38.8@4687.62,4904.1 4737.23,4854.49 C78.2@4750.51,4854.49
$3N84: CN1.5 R8.2 | length 103.2
  Bottom Layer w10: R8.2@3389.66,6605 3484.45,6605 CN1.5@3490.4,6599.05
$3N161: R80.2 U61.3 | length 245.2
  Inner2 w10: v1(4975,6720) 5130,6720 v1(5145,6735)
  Bottom Layer w10: U61.3@4914.33,6740 4955,6740 v1(4975,6720)
$3N180: LED8.1 R81.2 | length 71.9
  Bottom Layer w10: R81.2@5229.66,6645 LED8.1@5301.54,6645
$3N220: LED2.1 U61.24 | length 92.2
  Bottom Layer w39.37: LED2.1@4113.46,6140 U61.24@4205.67,6140
$3N4369: R69.1 U37.13 | length 99.1
  Top Layer w10: U37.13@5508.03,4816.02 5543.98,4816.02 5585.35,4774.65 R69.1@5585.35,4770
$3N4370: R68.1 U37.14 | length 82.1
  Top Layer w10: U37.14@5508.03,4841.61 5548.39,4841.61 5560,4830 R68.1@5585.35,4830
$3N4371: R67.1 U37.15 | length 86.8
  Top Layer w10: U37.15@5508.03,4867.2 5562.55,4867.2 R67.1@5585.35,4890
$3N4372: JP17.2 U38.12 | length 161.5
  Top Layer w15.75: U38.12@4645.9,4987.62 4665,5006.72 4665,5025 4715,5075 JP17.2@4760.47,5075
$3N4373: JP16.2 U38.13 | length 303.4
  Top Layer w15.75: JP16.2@4409.53,5090 4425.28,5105.75 4485.56,5105.75 4498.67,5118.86 4501.18,5118.86 4501.89,5119.57 4543.76,5119.57 4559.51,5103.82 4559.51,5061.17 4574.57,5046.11 4574.57,5017.13 U38.13@4604.11,4987.62
$3N4388: FPC1.1 JP7.1 | length 145.8
  Bottom Layer w10: JP7.1@5120.59,6450 5165,6450 5195.4,6479.6 FPC1.1@5254.35,6479.64
$3N4389: FPC1.2 R66.2 | length 191.3
  Bottom Layer w10: R66.2@5123.95,6345.71 5133.95,6355.71 5133.95,6378.95 5212.16,6457.16 5251.55,6457.16 FPC1.2@5254.35,6459.96
$3N4390: FPC1.3 R65.2 | length 247.3
  Bottom Layer w10: R65.2@5123.95,6275.71 5123.95,6309.87 5131.8,6317.72 5144.38,6317.72 5150.81,6324.15 5150.81,6373.21 5215.08,6437.48 5251.56,6437.48 FPC1.3@5254.35,6440.27
$3N4391: FPC1.4 R64.2 | length 284.3
  Bottom Layer w10: R64.2@5123.95,6210.71 5123.95,6227.29 5150.81,6254.15 5150.81,6257.57 5156.79,6263.55 5156.79,6307.53 5166.79,6317.53 5166.79,6366.58 5221.71,6421.5 5253.44,6421.5 FPC1.4@5254.35,6420.59
$3N4392: FPC1.5 R63.2 | length 324.6
  Bottom Layer w10: R63.2@5123.95,6145.71 5185,6206.76 5185,6357.92 5227.98,6400.9 FPC1.5@5254.35,6400.9
$3N4395: Q2.1 R60.1 R62.1 | length 132.5
  Bottom Layer w10: R62.1@5040.97,5920.97 5101.31,5920.97 R60.1@5110,5929.66 5110,5978.78 Q2.1@5102.4,5986.38
$3N4408: CN1.4 R84.1 | length 3451.8
  Top Layer w3.94: R84.1@4429.03,4874.03 4434.27,4868.78 4515.32,4868.78 4535,4888.46 4535,4930 v1(4525,4940)
  Top Layer w10: v5(3975,6595) 4024.39,6545.61 4024.39,6423 4097.55,6349.84 4123.22,6349.84 4222.36,6250.7 4222.36,6225.03 4329.02,6118.38 4329.02,6094.02 v1(4315,6080) 4315,5790 4345,5760 v1(4400,5760)
  Inner2 w10: v1(4415,5290) 4415,5264.02 4464.02,5215 4464.02,5145.2 v1(4456.14,5137.32)
  Inner3 w10: v1(4400,5760) 4444.02,5804.02 4519.65,5804.02 4593.19,5730.48 4593.19,5684.75 4634.75,5643.19 4680.48,5643.19 4732.15,5591.52 4732.15,5575.86 4723.97,5567.68 4583.38,5567.68 4564.02,5548.31 4564.02,5518.38 4574.19,5508.21 4574.19,5493.06 4415,5333.87 v1(4415,5290) ; v1(4456.14,5137.32) 4456.14,5087.65 4536.46,5007.32 4569.93,5007.32 4606.19,5043.59 4758.8,5043.59 4770.58,5055.37 4808.02,5055.37 4824.02,5039.38 4824.02,5018 4813.7,5007.68 4799.04,5007.68 4791.97,5000.61 4729.94,5000.61 4729.72,5000.39 4700.39,5000.39 4655,4955 4540,4955 v1(4525,4940)
  Bottom Layer w19.68: CN1.4@3789.6,6665.98 3901.96,6665.98 3972.94,6595 v5(3975,6595)
$3N4409: CN1.3 R83.1 | length 4009
  Top Layer w10: v5(3990,6740) 4040.38,6689.62 4040.38,6429.62 4104.17,6365.83 4129.84,6365.83 4238.35,6257.32 4238.35,6231.65 4345,6125 4345,5845 v1(4370,5820) ; R83.1@4575.34,4785 4581.3,4779.04 4581.3,4702.26 4587.73,4695.83 4646.92,4695.83 4653.06,4701.97 4731.97,4701.97 4741.74,4711.74 v1(4741.74,4716.67)
  Inner2 w10: v1(4440,5284.02) 4480,5244.02 v1(4480,5133.03)
  Inner3 w10: v1(4370,5820) 4526.27,5820 4609.17,5737.1 4609.17,5691.37 4641.37,5659.17 4687.1,5659.17 4748.14,5598.14 4748.14,5568.14 4731.69,5551.69 4590,5551.69 4580,5541.69 4580,5525 4600,5505 4600,5480 4570,5450 4553.73,5450 4438.6,5334.87 4438.6,5285.41 v1(4440,5284.02) ; v1(4480,5133.03) 4480,5086.39 4543.09,5023.31 4563.31,5023.31 4599.57,5059.57 4752.18,5059.57 4763.98,5071.37 4814.63,5071.37 4840,5046 4840,5010 4821.69,4991.69 4811.32,4991.69 4804.04,4984.4 4750.92,4984.4 4750.7,4984.62 4736.56,4984.62 4715,4963.06 4715,4897.72 4736.42,4876.3 4736.42,4736.74 4741.74,4731.43 v1(4741.74,4716.67)
  Bottom Layer w19.68: CN1.3@3490.4,6835.27 3894.73,6835.27 v5(3990,6740)
$3N4420: R5.1 R6.1 | length 100.6
  Top Layer w10: R6.1@4220,4951.78 4298.22,4951.78 R5.1@4314.03,4935.97
$3N4431: LED5.1 R74.2 | length 66.9
  Top Layer w39.37: LED5.1@4998.46,4960 R74.2@5065.34,4960
$3N4480: Q3.1 R77.2 | length 347.2
  Bottom Layer w29.53: Q3.1@5704.05,6561.6 5720,6577.55 5720,6760 5785.72,6825.72 R77.2@5835,6825.72
$3N4531: JP9.1 U61.2 | length 112.5
  Bottom Layer w23.62: U61.2@4914.33,6790 5020.59,6790 JP9.1@5025,6785.59
$3N4532: JP8.1 R80.1 | length 68.9
  Bottom Layer w10: R80.1@5204.66,6735 5259.41,6735 JP8.1@5269.41,6745
$3N4537: FPC4.1 JP15.1 | length 102.8
  Bottom Layer w10: FPC4.1@3775.53,5279.57 3810.43,5279.57 3820,5270 3820,5215.59
$3N4538: FPC4.2 JP14.1 | length 98.3
  Bottom Layer w10: FPC4.2@3775.53,5299.25 3858.66,5299.25 JP14.1@3869.41,5310
$3N4539: FPC4.30 JP13.1 | length 101.5
  Bottom Layer w10: FPC4.30@3775.53,5850.43 3836.02,5850.43 JP13.1@3865,5879.41
$3N18001: LED2.2 R40.1 | length 81.9
  Bottom Layer w39.37: R40.1@3964.66,6140 LED2.2@4046.53,6140
+5V: C129.2 C130.1 JP15.2 R22.1 U13.6 | length 3454.2
  Top Layer w19.68: v2(4030,4460) 4044.33,4445.67 4085.63,4445.67 4195.51,4335.79 4195.51,4234.21 4140,4178.7 v2(4140,4160)
  Inner3 w16: v2(4140,4160) 4055,4075 4055,3780 4350,3485 4350,3465.73 4435.73,3380 4770,3380 4800,3410 4800,3535 4759.02,3575.98 v2(4759.02,3900.36)
  Inner3 w19.68: v2(3739.71,5143.11) 3722.8,5126.2 3722.8,4767.2 3993.46,4496.54 3993.92,4496.54 4006.54,4483.92 4006.54,4483.46 v2(4030,4460)
  Bottom Layer w19.68: v2(3739.71,5143.11) 3767.07,5170.47 JP15.2@3825,5170.47
  Bottom Layer w20: C130.1@4760,3917.7 4780,3937.7 U13.6@4780,3980
  Bottom Layer w25: R22.1@4680,3865.34 4707.64,3865.34 C130.1@4760,3917.7 C129.2@4855,3917.7
AMP_EN: JP16.1 R6.2 U44.100 | length 1135.1
  Top Layer w10: JP16.1@4354.41,5090 4360,5095.59 4360,5140 4377.5,5157.5 4495.93,5157.5 4515,5138.43 4578.43,5138.43 4625,5185 v1(4625,5235)
  Top Layer w15.75: R6.2@4220,5068.22 4334.38,5068.22 4349.08,5082.92 4349.08,5084.67 JP16.1@4354.41,5090
  Bottom Layer w10: v1(4625,5235) 4634.02,5244.02 4765.98,5244.02 4783.31,5226.69 4831.69,5226.69 4841.69,5236.69 4841.69,5267.62 4831.69,5277.62 4831.69,5361.69 4870,5400 4989.47,5400 U44.100@5027.9,5438.43
AMP_G0: U38.6 U44.92 | length 1589.2
  Top Layer w10: U38.6@4659.83,4876.31 4662.23,4876.31 v1(4667.68,4870.86)
  Inner2 w10: v1(4281.89,5166.89) 4281.89,5110.71 4405.8,4986.8 v1(4406.8,4986.8)
  Inner3 w10: v1(4281.89,5166.89) 4285,5170 4831.3,5170 4939.02,5277.71 4939.02,5365.98 v1(4860,5445) ; v1(4406.8,4986.8) 4411.14,4982.46 ; 4411.14,4982.39 4420.51,4973.03 ; 4420.55,4973.03 4420.55,4961.67 4436.64,4945.58 4448.03,4945.58 4508.36,4885.24 v1(4509.26,4885.24) 4653.3,4885.24 v1(4667.68,4870.86)
  Bottom Layer w10: v1(4860,5445) 4860,5493.24 U44.92@4916.54,5549.78
AMP_G1: U38.7 U44.93 | length 1816.3
  Top Layer w10: v1(4298.59,5120) 4293.59,5115 4190,5115 4170,5095 4170,5038.6 4175.28,5033.32 4241.68,5033.32 4285.35,4989.65 4322.55,4989.65 4403.93,4908.26 4436.74,4908.26 4463.26,4881.74 4482.15,4881.74 4505.86,4905.45 v1(4520,4905.45) ; v1(4673.69,4889.87) U38.7@4673.69,4890.17
  Inner3 w10: v1(4298.59,5120) 4332.6,5154.02 4837.92,5154.02 4955,5271.09 4955,5375 v1(4880,5450) ; v1(4520,4905.45) 4658.12,4905.45 v1(4673.69,4889.87)
  Bottom Layer w10: v1(4880,5450) 4880,5485.4 U44.93@4930.46,5535.86
AMP_OUTL: C15.2 R84.2 U38.16 | length 196.3
  Top Layer w10: C15.2@4404.49,4950.51 4436.43,4950.51 R84.2@4470.97,4915.97 4515,4960 4548.29,4960 U38.16@4562.39,4945.9
AMP_OUTR: C16.1 R83.2 U38.5 | length 395
  Top Layer w10: R83.2@4634.66,4785 4634.66,4774.66 4605,4745 4605,4722.56 4607.56,4720 4688.83,4720 4750.16,4781.33 4750.16,4799.84 4709.02,4840.98 4667.3,4840.98 U38.5@4645.9,4862.38
B+: C85.2 U31.2 U32.1 U33.2 U33.3 | length 5349
  Top Layer w98.43: v5(4240,3475) 4240,3612.44 4250,3622.44 ; v5(4250,3700) 4250,3622.44 ; 4318.17,3712.44 4340,3712.44 4250,3622.44
  Inner2 w98.43: v5(3425,5295.47) v5(3425,5245) v5(3425,5190) 3425,5160 3510,5075 3510,4625 3375,4490 3375,4320 3473.93,4221.07 3594.8,4221.07 3709.8,4106.07 3709.8,3750.2 3985,3475 v5(4240,3475)
  Inner3 w66.93: U32.1@4044.37,7060 4044.37,6935.63 4045,6935
  Inner3 w98.43: v5(3425,5190) v5(3425,5245) v5(3425,5295.47) 3425,5750 3875.4,6200.4 3875.4,6775.4 3945,6845 4007.72,6845 4045,6882.28 4045,6935 ; 3905,6480 v5(3940,6480)
  Bottom Layer w20: C85.2@4340,3712.44 4407.56,3712.44 4410,3710
  Bottom Layer w39.37: U31.2@3865,6424.66 3865,6455 3890,6480 v5(3940,6480) ; v5(4250,3700) 4300,3700 4312.44,3712.44 C85.2@4340,3712.44
B_ADC: U30.2 U31.1 U44.34 | length 1566.5
  Inner2 w10: v1(3900,5985) 3780,5865 3780,5545 3810,5515 3830,5515 3850,5495 3850,5475 v1(3970,5355)
  Inner3 w10: v1(3970,5355) 4001.19,5323.81 v1(4001.19,5210)
  Bottom Layer w10: U31.1@3865,6365.34 3899.63,6365.34 ; v1(3900,5985) 3875,5985 3840,6020 3840,6170 3899.63,6229.63 3899.63,6365.34 ; U30.2@3935,6365.34 3899.63,6365.34 ; v1(4001.19,5210) 4001.19,5189.4 4034.6,5155.98 4049.48,5155.98 U44.34@4078.59,5185.09
B_B1: R87.1 SW3.1 SW3.2 U44.88 | length 6008.7
  Top Layer w3.94: v1(3825,4105) 3825,4090 3830,4085 3935,4085 3940,4090 R87.1@3940,4129.66 ; v1(3911.43,4965) 3915,4968.57 3915,5040 3890,5065 3890,5205 3915,5230 3915,5345 3960,5390 4150,5390 4165,5405 4165,5520 4105,5580 v1(4105,5630) ; v1(4142.22,6288.66) 4014.92,6161.37 4014.92,5876 4155.92,5735 v1(4175,5735) ; v1(4948.31,5599.38) 5021.26,5599.38 5191.22,5769.34 5191.22,5770.16 5341.06,5920 5341.06,5971.16 v1(5337.03,5975.19)
  Top Layer w10: SW3.1@3646.89,4127.83 SW3.2@3883.11,4127.83 3938.17,4127.83 3940,4129.66 R87.1@3940.34,4130
  Inner2 w3.94: v1(3825,4105) 3830,4110 3830,4390 3810,4410 3810,4510 3798.66,4521.34 3798.66,4852.23 v1(3911.43,4965) ; v1(4142.22,6288.66) 4158.55,6305 4250,6305 4415,6470 4415,6645 4435,6665 4740,6665 4835,6570 5115,6570 5160,6615 5235,6615 5245,6605 v1(5255,6605)
  Inner3 w3.94: v1(4105,5630) 4105,5665 v1(4175,5735) ; v1(5255,6605) 5430,6430 5430,6068.16 v1(5337.03,5975.19)
  Bottom Layer w3.94: U44.88@4860.87,5605.46 4890,5634.59 4890,5635 4892.78,5637.78 4898.9,5637.78 4937.3,5599.38 v1(4948.31,5599.38)
B_B2: R88.1 SW8.1 SW8.2 U44.89 | length 4086.5
  Top Layer w3.94: v1(3954.72,4951.77) 3954.72,4965.28 3924.92,4995.08 3924.92,5060.08 3899.92,5085.08 3899.92,5150 3924.92,5175 3924.92,5340.89 3959.11,5375.08 4095.06,5375.08 4112.41,5357.72 4131.75,5357.72 4174.92,5400.89 4174.92,5590.08 v1(4125,5640) ; v1(3965,4735) 3984.66,4715.34 R88.1@3984.66,4525 ; v1(4812.32,5490) 4812.32,5680.64 4942.05,5810.37 4942.05,6017.05 v1(4975,6050)
  Top Layer w10: R88.1@3984.66,4525 4039.06,4525 SW8.1@4041.89,4527.83 SW8.2@4278.11,4527.83
  Inner2 w3.94: v1(3954.72,4951.77) 3952.96,4950 3910.46,4950 3808.58,4848.12 3808.58,4776.6 3825.18,4760 3940,4760 v1(3965,4735)
  Bottom Layer w3.94: v1(4125,5640) 4125,5645 4199.55,5719.55 4199.55,5827.87 4514.63,6142.95 4715.37,6142.95 4785.37,6072.95 4805.37,6072.95 4846.87,6031.45 4846.87,5925 4861.87,5910 4957.89,5910 4975,5927.11 v1(4975,6050) ; v1(4812.32,5490) 4824.17,5501.85 4824.17,5513.31 4840,5529.14 4840,5556.76 U44.89@4874.78,5591.54
B_VIN: C51.2 C126.2 C131.2 C132.2 R31.2 R34.1 R35.1 TP11.1 U13.2 U13.3 U33.5 U67.10 U67.11 U68.2 | length 4548.5
  Top Layer w19.68: v2(5755,6505) 5710,6550 5710,6660 5750,6700 5815,6700 5835.74,6720.74 TP11.1@5835.74,6743.56
  Inner3 w16: v2(4324.66,3905) 4415,3814.66 v2(4415,3800) 4440,3825 v2(4515.59,3825) 4517.37,3823.22 v2(4600,3823.22) 4630,3853.22 4630,3970.63 v2(4654.37,3995) ; v2(4720.15,4025) 4720.15,4025.15 4744.85,4049.85 4860.15,4049.85 4887.6,4022.4 v2(4887.6,4010)
  Inner3 w19.68: v2(4887.6,4010) 5195,4317.4 5195,4550 5458.85,4813.85 5458.85,4998.85 5765,5305 5765,6495 v2(5755,6505)
  Bottom Layer w12: v2(4654.37,3995) 4670,3995 4700,4025 v2(4720.15,4025) U13.3@4720.47,4024.68
  Bottom Layer w13: U13.2@4720.47,4005 U13.3@4720.47,4024.68
  Bottom Layer w15: R35.1@4185,3889.66 4204.66,3870 4310,3870 4324.66,3884.66 v2(4324.66,3905) 4327.7,3905 C126.2@4407.7,3985
  Bottom Layer w16: v2(4415,3800) 4435.48,3779.52 U33.5@4435.48,3769.05
  Bottom Layer w19.68: 4379.94,4050 4379.94,4012.76 C126.2@4407.7,3985
  Bottom Layer w20: v2(4654.37,3995) 4689.37,4030 C132.2@4689.37,4080
CAPM: C36.2 U37.4 | length 77.4
  Top Layer w10: C36.2@5205,4917.44 5205.95,4918.39 U37.4@5281.97,4918.39
CAPP: C36.1 U37.2 | length 78.2
  Top Layer w10: C36.1@5205,4972.56 5207.99,4969.57 U37.2@5281.97,4969.57
CC_CSN: FPC4.21 U44.76 | length 1141.2
  Inner2 w10: v1(3815,5673.27) 4348.27,5673.27 4560,5885 4695,5885 v1(4720,5860)
  Bottom Layer w10: FPC4.21@3775.53,5673.27 v1(3815,5673.27) ; U44.76@4693.83,5772.49 4720.35,5799.01 4720.35,5817.18 4720,5817.53 v1(4720,5860)
CC_GDO0: FPC4.20 U44.139 | length 1455.3
  Inner2 w10: v1(3815,5653.58) 3889.1,5653.58 4090,5452.68 4090,5365 4120,5335 4207.68,5335 4636.11,4906.57 4729.76,4906.57 v1(4732.82,4903.51)
  Bottom Layer w10: FPC4.20@3775.53,5653.58 v1(3815,5653.58) ; U44.139@4721.67,4795.35 4719.65,4795.35 4695.15,4819.85 4695.15,4840.03 4707.01,4851.89 4707.01,4877.69 v1(4732.82,4903.51)
CC_GDO2: FPC4.19 U44.137 | length 1516.6
  Inner2 w10: v1(3815,5633.9) 3815.92,5634.82 3885.25,5634.82 4065,5455.07 4065,5360 4115,5310 4185,5310 4471.51,5023.49 4496.56,5023.49 4610.99,4909.06 4610.99,4884.01 4666.69,4828.31 4691.95,4828.31 4753.13,4889.49 v1(4753.13,4899.01)
  Bottom Layer w10: FPC4.19@3775.53,5633.9 v1(3815,5633.9) ; U44.137@4749.51,4823.19 4722.99,4849.71 4722.99,4867.87 4753.13,4898.01 v1(4753.13,4899.01)
CC_MISO: FPC4.18 U44.42 | length 527.8
  Bottom Layer w10: FPC4.18@3775.53,5614.21 v1(3815,5614.21) 3882.7,5614.21 3889.66,5621.17 4012.2,5621.17 4116.69,5516.68 4116.69,5486.53 4093.82,5463.66 4093.82,5427.42 4120.35,5400.89 U44.42@4120.35,5396.67
CC_MOSI: FPC4.17 U44.43 | length 435.5
  Top Layer w10: v1(3960,5475) 4069.85,5475 v1(4134.26,5410.59)
  Bottom Layer w10: FPC4.17@3775.53,5594.53 v1(3815,5594.53) 3840.47,5594.53 3855.77,5579.23 3856.81,5579.23 3960,5476.04 v1(3960,5475)
CC_SCK: FPC4.16 U44.133 | length 1604.5
  Inner2 w10: v1(3815,5574.84) 3922.63,5574.84 4043.85,5453.62 4043.85,5348.76 4105.34,5287.27 4185.13,5287.27 4464.89,5007.51 4489.91,5007.51 4595.01,4902.41 4595.01,4877.39 4660.07,4812.32 4698.57,4812.32 4737.23,4850.98 4780.98,4850.98 4791.69,4861.69 4791.69,4910.83 4777.91,4924.61 4766.78,4924.61 v1(4754.59,4936.81)
  Bottom Layer w10: FPC4.16@3775.53,5574.84 v1(3815,5574.84) ; v1(4754.59,4936.81) 4778.72,4912.67 4778.72,4905.33 U44.133@4805.19,4878.86
CK: R106.1 U44.48 | length 1786.2
  Inner2 w10: v1(4888.19,4788.65) 4890.81,4791.27 4897.74,4791.27 4901.7,4787.3 4957.3,4787.3 4967.01,4797.01 5029.8,4797.01 5041.18,4785.63 5055.01,4785.63 5065.01,4795.63 5113.14,4795.63 v1(5117.09,4791.68) ; v1(5193.31,4758.39) 5196.7,4755 5209.71,4755 5251.97,4712.74 5251.97,4500.99 v2(5270,4482.96)
  Inner3 w10: v1(4801.69,4955) 4802.8,4953.89 4810.69,4953.89 4820.69,4943.89 4820.69,4845.53 4877.57,4788.65 v1(4888.19,4788.65) ; v1(5117.09,4791.68) 5110.15,4791.68 5091.98,4773.51 5091.98,4763.51 5099.05,4756.44 5163.4,4756.44 5164.52,4755.32 5174.52,4755.32 5177.6,4758.39 v1(5193.31,4758.39)
  Bottom Layer w10: U44.48@4203.86,5480.19 4231.76,5452.29 4235.82,5452.29 4310,5378.11 4310,5304.23 4384.15,5230.08 4535,5230.08 4801.69,4963.39 v1(4801.69,4955)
